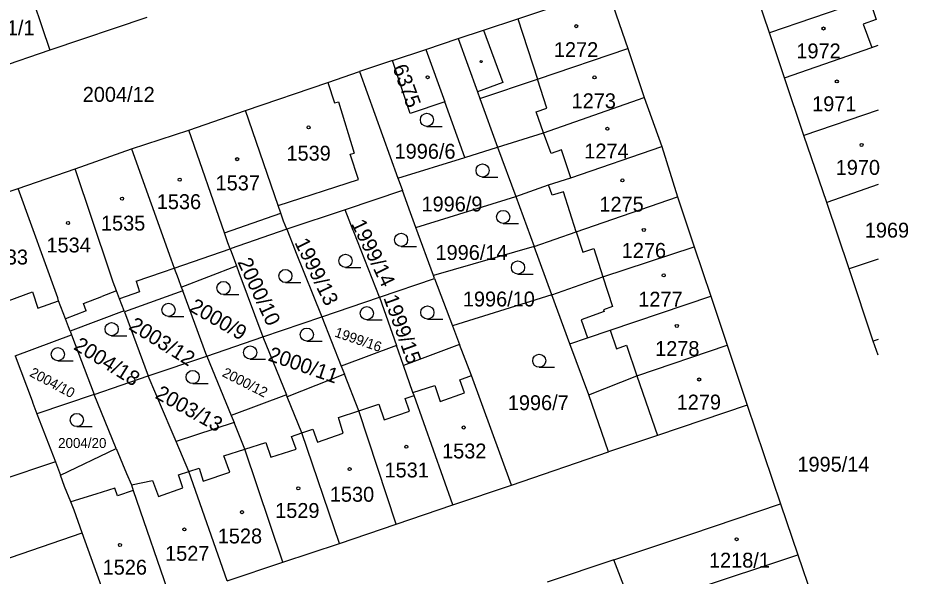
# Model space of a CAD drawing. Extents: x -564952 to -564307, y -1202373 to -1201847.
# Drawn here: x -564412.8 to -564311.2, y -1202155 to -1202091.3 of the extents above; entities that cross this region are included whole.
import ezdxf

# ---------------------------------------------------------------- set-up
doc = ezdxf.new("R2010")
doc.units = 0
for name, color, linetype in [('Hranice parcel', 7, 'Continuous'), ('Parcelní čísla', 7, 'Continuous'), ('Vnitřní kresba', 7, 'Continuous'), ('Značky budov', 7, 'Continuous'), ('Značky kultur', 7, 'Continuous')]:
    doc.layers.add(name, color=color, linetype=linetype)

msp = doc.modelspace()

# ---------------------------------------------------------------- linework, layer by layer
at = {"layer": 'Hranice parcel'}
for p, q in [((-564327.05, -1202093.01), (-564330.1, -1202083.96)), ((-564355.78, -1202091.38), (-564345.58, -1202087.99)), ((-564345.58, -1202087.99), (-564343.21, -1202094.78)), ((-564398.11, -1202091.24), (-564409.17, -1202094.97)), ((-564325.33, -1202098.13), (-564327.05, -1202093.01)), ((-564366.26, -1202094.88), (-564362.59, -1202093.65)), ((-564409.17, -1202094.97), (-564416.99, -1202097.64)), ((-564370.08, -1202096.16), (-564366.26, -1202094.88)), ((-564366.26, -1202094.88), (-564364.09, -1202100.88)), ((-564343.21, -1202094.78), (-564341.34, -1202100.38)), ((-564370.08, -1202096.16), (-564373.83, -1202097.42)), ((-564368.05, -1202102.21), (-564370.08, -1202096.16)), ((-564373.83, -1202097.42), (-564369.45, -1202109.57)), ((-564323.12, -1202104.71), (-564325.33, -1202098.13)), ((-564341.34, -1202100.38), (-564339.35, -1202105.98)), ((-564364.09, -1202100.88), (-564368.05, -1202102.21)), ((-564361.81, -1202107.21), (-564364.09, -1202100.88)), ((-564393.32, -1202104.11), (-564386.86, -1202101.86)), ((-564314.65, -1202101.83), (-564323.12, -1202104.71)), ((-564399.87, -1202106.23), (-564393.32, -1202104.11)), ((-564320.52, -1202112.35), (-564323.12, -1202104.71)), ((-564406.3, -1202108.52), (-564399.87, -1202106.23)), ((-564399.87, -1202106.23), (-564395.37, -1202118.77)), ((-564361.81, -1202107.21), (-564358.07, -1202106.05)), ((-564358.07, -1202106.05), (-564356.01, -1202111.68)), ((-564339.35, -1202105.98), (-564337.55, -1202111.69)), ((-564369.45, -1202109.57), (-564361.81, -1202107.21)), ((-564412.8, -1202110.76), (-564406.3, -1202108.52)), ((-564369.45, -1202109.57), (-564369.31, -1202109.97)), ((-564369.31, -1202109.97), (-564368.94, -1202110.98)), ((-564314.65, -1202110.31), (-564320.52, -1202112.35)), ((-564419.59, -1202113.07), (-564412.8, -1202110.76)), ((-564368.94, -1202110.98), (-564375.49, -1202113.18)), ((-564368.01, -1202113.53), (-564368.94, -1202110.98)), ((-564367.39, -1202115.22), (-564356.01, -1202111.68)), ((-564356.01, -1202111.68), (-564353.91, -1202117.36)), ((-564337.55, -1202111.69), (-564335.66, -1202117.4)), ((-564317.96, -1202119.94), (-564320.52, -1202112.35)), ((-564375.49, -1202113.18), (-564382.14, -1202115.41)), ((-564367.39, -1202115.22), (-564368.01, -1202113.53)), ((-564382.14, -1202115.41), (-564382.52, -1202114.47)), ((-564382.14, -1202115.41), (-564388.61, -1202117.64)), ((-564365.4, -1202120.7), (-564367.39, -1202115.22)), ((-564388.61, -1202117.64), (-564387.89, -1202119.58)), ((-564353.91, -1202117.36), (-564365.4, -1202120.7)), ((-564351.88, -1202122.89), (-564353.91, -1202117.36)), ((-564335.66, -1202117.4), (-564333.75, -1202123.03)), ((-564394.17, -1202122), (-564387.89, -1202119.58)), ((-564365.28, -1202121.04), (-564365.4, -1202120.7)), ((-564315.2, -1202128.18), (-564317.96, -1202119.94)), ((-564394.54, -1202121.02), (-564394.17, -1202122)), ((-564371.54, -1202123.17), (-564365.28, -1202121.04)), ((-564365.28, -1202121.04), (-564363.22, -1202126.43)), ((-564394.01, -1202122.45), (-564400.66, -1202124.84)), ((-564394.17, -1202122), (-564394.01, -1202122.45)), ((-564391.26, -1202129.88), (-564394.01, -1202122.45)), ((-564378.14, -1202125.42), (-564371.54, -1202123.17)), ((-564371.54, -1202123.17), (-564369.61, -1202128.66)), ((-564351.88, -1202122.89), (-564363.22, -1202126.43)), ((-564349.85, -1202128.48), (-564351.88, -1202122.89)), ((-564333.75, -1202123.03), (-564331.88, -1202128.64)), ((-564400.71, -1202124.7), (-564406.86, -1202127.03)), ((-564400.66, -1202124.84), (-564400.71, -1202124.7)), ((-564400.66, -1202124.84), (-564397.94, -1202132.15)), ((-564384.86, -1202127.7), (-564378.14, -1202125.42)), ((-564378.14, -1202125.42), (-564375.91, -1202131.05)), ((-564363.22, -1202126.43), (-564362.41, -1202128.56)), ((-564413.14, -1202129.85), (-564406.69, -1202127.47)), ((-564406.86, -1202127.03), (-564406.69, -1202127.47)), ((-564406.69, -1202127.47), (-564404.13, -1202134.26)), ((-564391.26, -1202129.88), (-564384.86, -1202127.7)), ((-564384.86, -1202127.7), (-564382.17, -1202134.31)), ((-564369.61, -1202128.66), (-564375.91, -1202131.05)), ((-564368.81, -1202130.94), (-564369.61, -1202128.66)), ((-564362.41, -1202128.56), (-564368.81, -1202130.94)), ((-564347.66, -1202134.31), (-564349.85, -1202128.48)), ((-564331.88, -1202128.64), (-564329.6, -1202135.47)), ((-564314.65, -1202129.79), (-564315.2, -1202128.18)), ((-564413.14, -1202129.85), (-564411.2, -1202134.99)), ((-564397.94, -1202132.15), (-564391.26, -1202129.88)), ((-564391.26, -1202129.88), (-564388.48, -1202136.67)), ((-564375.56, -1202131.94), (-564382.08, -1202134.54)), ((-564375.91, -1202131.05), (-564375.56, -1202131.94)), ((-564404.13, -1202134.26), (-564397.94, -1202132.15)), ((-564404.13, -1202134.26), (-564410.64, -1202136.47)), ((-564401.59, -1202140.42), (-564404.13, -1202134.26)), ((-564382.17, -1202134.31), (-564388.48, -1202136.67)), ((-564382.08, -1202134.54), (-564382.17, -1202134.31)), ((-564345.41, -1202140.82), (-564347.66, -1202134.31)), ((-564329.6, -1202135.47), (-564325.78, -1202146.73)), ((-564410.64, -1202136.47), (-564408.53, -1202141.96)), ((-564388.48, -1202136.67), (-564388.15, -1202137.47)), ((-564388.15, -1202137.47), (-564394.75, -1202139.64)), ((-564407.95, -1202143.46), (-564401.59, -1202140.42)), ((-564356.49, -1202144.6), (-564345.41, -1202140.82)), ((-564408.53, -1202141.96), (-564407.95, -1202143.46)), ((-564407.49, -1202144.77), (-564407.95, -1202143.46)), ((-564363.18, -1202146.87), (-564356.49, -1202144.6)), ((-564369.64, -1202149.05), (-564363.18, -1202146.87)), ((-564325.78, -1202146.73), (-564323.81, -1202152.55)), ((-564376.1, -1202151.25), (-564369.64, -1202149.05)), ((-564382.59, -1202153.39), (-564376.1, -1202151.25)), ((-564344.81, -1202153.14), (-564352.41, -1202155.68)), ((-564323.81, -1202152.55), (-564321.87, -1202158.24)), ((-564388.94, -1202155.54), (-564382.59, -1202153.39))]:
    msp.add_line(p, q, dxfattribs=at)
for points in [[(-564412.56, -1202085.59), (-564412.16, -1202086.79), (-564411.96, -1202086.73), (-564409.17, -1202094.97)], [(-564314.65, -1202088.74), (-564315.68, -1202089.06), (-564317.24, -1202089.63), (-564327.05, -1202093.01)], [(-564362.59, -1202093.65), (-564359.67, -1202092.68), (-564355.78, -1202091.38)], [(-564362.59, -1202093.65), (-564360.37, -1202099.72), (-564360.1, -1202100.47)], [(-564360.1, -1202100.47), (-564353.54, -1202098.29), (-564343.21, -1202094.78)], [(-564325.33, -1202098.13), (-564315.36, -1202094.65), (-564314.65, -1202094.4)], [(-564386.86, -1202101.86), (-564377.46, -1202098.66), (-564373.83, -1202097.42)], [(-564358.07, -1202106.05), (-564352.82, -1202104.42), (-564341.34, -1202100.38)], [(-564382.52, -1202114.47), (-564382.83, -1202113.57), (-564383.13, -1202112.69), (-564386.86, -1202101.86)], [(-564388.61, -1202117.64), (-564388.86, -1202116.97), (-564389.26, -1202115.82), (-564393.32, -1202104.11)], [(-564356.01, -1202111.68), (-564352.26, -1202110.34), (-564349.71, -1202109.53), (-564339.35, -1202105.98)], [(-564400.71, -1202124.7), (-564400.96, -1202124.03), (-564401.23, -1202123.33), (-564401.55, -1202122.45), (-564401.93, -1202121.45), (-564402.31, -1202120.31), (-564406.3, -1202108.52)], [(-564408.17, -1202123.57), (-564408.28, -1202123.22), (-564412.8, -1202110.76)], [(-564353.91, -1202117.36), (-564349.09, -1202115.72), (-564337.55, -1202111.69)], [(-564371.54, -1202123.17), (-564374.5, -1202115.7), (-564374.55, -1202115.55), (-564375.49, -1202113.18)], [(-564382.14, -1202115.41), (-564381.17, -1202117.83), (-564381.13, -1202117.93), (-564378.14, -1202125.42)], [(-564351.88, -1202122.89), (-564346.05, -1202120.84), (-564335.66, -1202117.4)], [(-564395.37, -1202118.77), (-564394.97, -1202119.84), (-564394.54, -1202121.02)], [(-564387.89, -1202119.58), (-564387.61, -1202120.33), (-564384.86, -1202127.7)], [(-564314.65, -1202118.82), (-564317.96, -1202119.94)], [(-564406.86, -1202127.03), (-564407.05, -1202126.54), (-564407.39, -1202125.62), (-564408.17, -1202123.57)], [(-564349.85, -1202128.48), (-564347.81, -1202127.79), (-564345.21, -1202126.91), (-564333.75, -1202123.03)], [(-564356.49, -1202144.6), (-564361.07, -1202132.1), (-564362.41, -1202128.56)], [(-564347.66, -1202134.31), (-564342.17, -1202132.13), (-564331.88, -1202128.64)], [(-564314.65, -1202128), (-564315.2, -1202128.18)], [(-564369.64, -1202149.05), (-564373.91, -1202136.11), (-564375.56, -1202131.94)], [(-564363.18, -1202146.87), (-564367.6, -1202134.39), (-564367.73, -1202134.04), (-564368.81, -1202130.94)], [(-564394.75, -1202139.64), (-564395.32, -1202138.3), (-564397.94, -1202132.15)], [(-564411.2, -1202134.99), (-564411.1, -1202135.26), (-564410.64, -1202136.47)], [(-564376.1, -1202151.25), (-564380.41, -1202138.65), (-564382.08, -1202134.54)], [(-564329.6, -1202135.47), (-564339.84, -1202138.95), (-564345.41, -1202140.82)], [(-564382.59, -1202153.39), (-564386.91, -1202140.5), (-564388.15, -1202137.47)], [(-564388.94, -1202155.54), (-564393.3, -1202143.04), (-564394.75, -1202139.64)], [(-564401.59, -1202140.42), (-564400.42, -1202143.26), (-564399.87, -1202144.59), (-564399.66, -1202145.21), (-564395.37, -1202157.69)], [(-564408.53, -1202141.96), (-564414.93, -1202144.06), (-564419.54, -1202145.57)], [(-564401.92, -1202159.96), (-564405.48, -1202150.04), (-564406.41, -1202147.46), (-564406.78, -1202146.53), (-564407.49, -1202144.77)], [(-564344.81, -1202153.14), (-564340.24, -1202151.6), (-564336.01, -1202150.19), (-564325.78, -1202146.73)], [(-564341.55, -1202161.62), (-564341.65, -1202161.36), (-564344.81, -1202153.14)], [(-564338.02, -1202160.39), (-564339.1, -1202157.6), (-564336.63, -1202156.83), (-564336.05, -1202156.64), (-564323.81, -1202152.55)]]:
    msp.add_lwpolyline(points, dxfattribs=at)
at = {"layer": 'Vnitřní kresba'}
for p, q in [((-564315.68, -1202089.06), (-564314.87, -1202091.46)), ((-564355.78, -1202091.38), (-564353.54, -1202098.29)), ((-564314.87, -1202091.46), (-564316.35, -1202092.01)), ((-564316.35, -1202092.01), (-564315.36, -1202094.65)), ((-564359.67, -1202092.68), (-564357.49, -1202098.67)), ((-564352.47, -1202101.6), (-564353.54, -1202098.29)), ((-564377.46, -1202098.66), (-564376.67, -1202101)), ((-564357.49, -1202098.67), (-564360.37, -1202099.72)), ((-564376.67, -1202101), (-564376.24, -1202100.85)), ((-564376.24, -1202100.85), (-564374.45, -1202106.71)), ((-564360.1, -1202100.47), (-564358.07, -1202106.05)), ((-564353.67, -1202102.02), (-564352.47, -1202101.6)), ((-564352.82, -1202104.42), (-564353.67, -1202102.02)), ((-564351.98, -1202106.78), (-564352.82, -1202104.42)), ((-564350.79, -1202106.36), (-564351.98, -1202106.78)), ((-564349.71, -1202109.53), (-564350.79, -1202106.36)), ((-564374.89, -1202106.85), (-564374.45, -1202106.71)), ((-564373.96, -1202109.73), (-564374.89, -1202106.85)), ((-564383.13, -1202112.69), (-564373.96, -1202109.73)), ((-564351.85, -1202111.52), (-564352.26, -1202110.34)), ((-564350.57, -1202111.12), (-564351.85, -1202111.52)), ((-564349.09, -1202115.72), (-564350.57, -1202111.12)), ((-564389.26, -1202115.82), (-564382.83, -1202113.57)), ((-564349.09, -1202115.72), (-564348.35, -1202118.01)), ((-564394.97, -1202119.84), (-564388.61, -1202117.64)), ((-564348.35, -1202118.01), (-564347.1, -1202117.61)), ((-564347.1, -1202117.61), (-564346.05, -1202120.84)), ((-564399.34, -1202121.35), (-564396.33, -1202120.31)), ((-564396.33, -1202120.31), (-564394.97, -1202119.84)), ((-564399.34, -1202121.35), (-564398.93, -1202122.54)), ((-564346.05, -1202120.84), (-564344.95, -1202124.24)), ((-564413.93, -1202123.58), (-564411.16, -1202122.55)), ((-564411.16, -1202122.55), (-564410.56, -1202124.41)), ((-564401.55, -1202122.45), (-564403.25, -1202123.09)), ((-564398.93, -1202122.54), (-564401.23, -1202123.33)), ((-564410.56, -1202124.41), (-564408.17, -1202123.57)), ((-564405.34, -1202123.88), (-564403.25, -1202123.09)), ((-564405.02, -1202124.72), (-564407.39, -1202125.62)), ((-564405.02, -1202124.72), (-564405.34, -1202123.88)), ((-564345.93, -1202124.8), (-564348.52, -1202125.76)), ((-564344.95, -1202124.24), (-564346, -1202124.6)), ((-564346, -1202124.6), (-564345.93, -1202124.8)), ((-564348.52, -1202125.76), (-564347.81, -1202127.79)), ((-564345.21, -1202126.91), (-564344.49, -1202129.04)), ((-564344.49, -1202129.04), (-564343.36, -1202128.65)), ((-564343.36, -1202128.65), (-564342.17, -1202132.13)), ((-564362.39, -1202132.59), (-564361.07, -1202132.1)), ((-564361.85, -1202134.08), (-564362.39, -1202132.59)), ((-564342.17, -1202132.13), (-564339.84, -1202138.95)), ((-564367.73, -1202134.04), (-564365.23, -1202133.22)), ((-564365.23, -1202133.22), (-564364.62, -1202135.06)), ((-564368.64, -1202134.71), (-564367.6, -1202134.39)), ((-564368.12, -1202136.17), (-564368.64, -1202134.71)), ((-564364.62, -1202135.06), (-564361.85, -1202134.08)), ((-564373.91, -1202136.11), (-564371.63, -1202135.35)), ((-564371.63, -1202135.35), (-564371.03, -1202137.14)), ((-564376.25, -1202136.88), (-564373.91, -1202136.11)), ((-564375.69, -1202138.66), (-564376.25, -1202136.88)), ((-564371.03, -1202137.14), (-564368.12, -1202136.17)), ((-564381.58, -1202139.06), (-564380.41, -1202138.65)), ((-564381.07, -1202140.49), (-564381.58, -1202139.06)), ((-564380.41, -1202138.65), (-564379.16, -1202138.21)), ((-564379.16, -1202138.21), (-564378.63, -1202139.72)), ((-564378.63, -1202139.72), (-564375.69, -1202138.66)), ((-564386.91, -1202140.5), (-564384.52, -1202139.73)), ((-564384.52, -1202139.73), (-564383.97, -1202141.42)), ((-564389.3, -1202141.28), (-564386.91, -1202140.5)), ((-564383.97, -1202141.42), (-564381.07, -1202140.49)), ((-564388.64, -1202143.12), (-564389.3, -1202141.28)), ((-564394.49, -1202143.43), (-564393.3, -1202143.04)), ((-564393.3, -1202143.04), (-564392.13, -1202142.66)), ((-564392.13, -1202142.66), (-564391.66, -1202144.15)), ((-564391.66, -1202144.15), (-564388.64, -1202143.12)), ((-564399.87, -1202144.59), (-564397.45, -1202144.07)), ((-564397.45, -1202144.07), (-564396.78, -1202145.92)), ((-564394, -1202144.93), (-564394.49, -1202143.43)), ((-564401.74, -1202144.94), (-564403.91, -1202145.62)), ((-564401.44, -1202145.82), (-564401.74, -1202144.94)), ((-564396.78, -1202145.92), (-564394, -1202144.93)), ((-564403.91, -1202145.62), (-564406.78, -1202146.53)), ((-564399.66, -1202145.21), (-564401.44, -1202145.82)), ((-564414.78, -1202153.23), (-564405.48, -1202150.04))]:
    msp.add_line(p, q, dxfattribs=at)
at = {"layer": 'Značky budov'}
for centre, radius in [((-564349.1, -1202092.23), 0.175), ((-564320.88, -1202092.5), 0.175), ((-564359.95, -1202096.28), 0.117), ((-564366.06, -1202098.06), 0.175), ((-564347.02, -1202098.08), 0.175), ((-564319.36, -1202098.54), 0.175), ((-564379.65, -1202103.78), 0.175), ((-564345.55, -1202103.94), 0.175), ((-564316.54, -1202105.79), 0.175), ((-564387.8, -1202107.41), 0.175), ((-564394.35, -1202109.75), 0.175), ((-564343.83, -1202109.83), 0.175), ((-564400.93, -1202111.91), 0.175), ((-564407.1, -1202114.7), 0.175), ((-564341.39, -1202115.49), 0.175), ((-564339.12, -1202120.67), 0.175), ((-564337.62, -1202126.44), 0.175), ((-564335.07, -1202132.55), 0.175), ((-564361.94, -1202138.03), 0.175), ((-564368.5, -1202140.23), 0.175), ((-564374.96, -1202142.78), 0.175), ((-564380.82, -1202144.97), 0.175), ((-564387.24, -1202147.69), 0.175), ((-564393.82, -1202149.66), 0.175), ((-564401.17, -1202151.43), 0.175), ((-564330.8, -1202150.78), 0.175)]:
    msp.add_circle(centre, radius, dxfattribs=at)
at = {"layer": 'Značky kultur'}
for p, q in [((-564366.14, -1202103.67), (-564364.39, -1202103.67)), ((-564359.79, -1202109.45), (-564358.04, -1202109.45)), ((-564357.44, -1202114.75), (-564355.69, -1202114.75)), ((-564369.09, -1202117.37), (-564367.34, -1202117.37)), ((-564375.44, -1202119.76), (-564373.69, -1202119.76)), ((-564355.75, -1202120.52), (-564354, -1202120.52)), ((-564382.29, -1202121.49), (-564380.54, -1202121.49)), ((-564389.36, -1202122.86), (-564387.61, -1202122.86)), ((-564395.63, -1202125.36), (-564393.88, -1202125.36)), ((-564373, -1202125.74), (-564371.25, -1202125.74)), ((-564366.09, -1202125.66), (-564364.34, -1202125.66)), ((-564402.12, -1202127.56), (-564400.37, -1202127.56)), ((-564379.84, -1202128.18), (-564378.09, -1202128.18)), ((-564408.27, -1202130.42), (-564406.52, -1202130.42)), ((-564386.31, -1202130.22), (-564384.56, -1202130.22)), ((-564353.32, -1202131.16), (-564351.57, -1202131.16)), ((-564392.87, -1202133.02), (-564391.12, -1202133.02)), ((-564406.1, -1202137.93), (-564404.35, -1202137.93))]:
    msp.add_line(p, q, dxfattribs=at)
for centre in [(-564366.14, -1202102.92), (-564359.79, -1202108.7), (-564357.44, -1202114), (-564369.09, -1202116.62), (-564375.44, -1202119.01), (-564355.75, -1202119.77), (-564382.29, -1202120.74), (-564389.36, -1202122.11), (-564395.63, -1202124.61), (-564373, -1202124.99), (-564366.09, -1202124.91), (-564402.12, -1202126.81), (-564379.84, -1202127.43), (-564386.31, -1202129.47), (-564408.27, -1202129.67), (-564353.32, -1202130.41), (-564392.87, -1202132.27), (-564406.1, -1202137.18)]:
    msp.add_circle(centre, 0.75, dxfattribs=at)

# ---------------------------------------------------------------- texts
at = {"layer": 'Parcelní čísla'}
for s, height, p in [('1611/1', 1.7, (-564417.88, -1202093.27)), ('1272', 1.7, (-564351.65, -1202095.76)), ('1972', 1.7, (-564323.98, -1202095.91)), ('2004/12', 1.7, (-564405.42, -1202100.87)), ('1273', 1.7, (-564349.63, -1202101.6)), ('1971', 1.7, (-564322.18, -1202101.94)), ('1539', 1.7, (-564382.17, -1202107.58)), ('1996/6', 1.7, (-564369.83, -1202107.36)), ('1274', 1.7, (-564348.18, -1202107.33)), ('1970', 1.7, (-564319.49, -1202109.2)), ('1537', 1.7, (-564390.26, -1202110.97)), ('1536', 1.7, (-564396.97, -1202113.11)), ('1996/9', 1.7, (-564366.76, -1202113.38)), ('1275', 1.7, (-564346.46, -1202113.4)), ('1535', 1.7, (-564403.34, -1202115.56)), ('1969', 1.7, (-564316.17, -1202116.36)), ('1534', 1.7, (-564409.56, -1202118.06)), ('1533', 1.7, (-564416.73, -1202119.43)), ('1996/14', 1.7, (-564365.16, -1202118.91)), ('1276', 1.7, (-564343.91, -1202118.67)), ('1996/10', 1.7, (-564362.04, -1202124.22)), ('1277', 1.7, (-564342.02, -1202124.24)), ('1278', 1.7, (-564340.1, -1202129.87)), ('1996/7', 1.7, (-564356.91, -1202136.05)), ('1279', 1.7, (-564337.64, -1202135.98)), ('2004/20', 1.14, (-564408.23, -1202140.37)), ('1532', 1.7, (-564364.41, -1202141.56)), ('1531', 1.7, (-564370.98, -1202143.73)), ('1995/14', 1.7, (-564323.86, -1202143.07)), ('1530', 1.7, (-564377.22, -1202146.5)), ('1529', 1.7, (-564383.46, -1202148.35)), ('1528', 1.7, (-564390.01, -1202151.26)), ('1527', 1.7, (-564396.02, -1202153.24)), ('1218/1', 1.7, (-564333.95, -1202154.02)), ('1526', 1.7, (-564403.15, -1202154.82))]:
    msp.add_text(s, height=height, dxfattribs=at).set_placement(p)
for s, height, rotation, p in [('6375', 1.7, 290, (-564370.09, -1202096.94)), ('1999/14', 1.7, 296, (-564374.82, -1202114.77)), ('1999/13', 1.7, 296, (-564381.29, -1202116.91)), ('2000/10', 1.7, 295, (-564387.79, -1202119.14)), ('2000/9', 1.7, 330, (-564393.37, -1202124.67)), ('1999/15', 1.7, 290, (-564371.13, -1202123.22)), ('2003/12', 1.7, 328, (-564400.28, -1202126.76)), ('1999/16', 1.14, 341, (-564376.76, -1202127.63)), ('2004/18', 1.7, 328, (-564406.57, -1202129.04)), ('2000/11', 1.7, 341, (-564384.38, -1202130.36)), ('2004/10', 1.14, 332, (-564411.58, -1202132.12)), ('2000/12', 1.14, 333, (-564389.6, -1202132.14)), ('2003/13', 1.7, 331, (-564397.26, -1202134.62))]:
    msp.add_text(s, height=height, rotation=rotation, dxfattribs=at).set_placement(p)

doc.saveas('drawing.dxf')
